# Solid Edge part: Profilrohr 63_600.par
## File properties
Username: ahadarics
Dokumentum tartalom típus: 0
Author: ahadarics
Last saved by: ahadarics
Revision: 93
Sűrűség: 0,000 kg/m^3
Pontosság: 0,990
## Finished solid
Body 1: solid body, 175 faces, 519 edges, 346 vertices.
  Faces by surface: cylinder 107, plane 68
  Edges by curve: line 305, circle 214
Bounding box of the edges (mm): 70.400 x 70.400 x 654.000, from (-35.2, -35.2, -614.5) to (35.2, 35.2, 39.5).
Cylindrical faces by radius (mm): R0.1 x16, R0.2 x30, R0.5 x28, R1 x8, R3.75 x8, R4.8 x4, R6 x4, R31.5 x1, R33.8 x8
Planar faces by outward normal: +x 6, +y 6, +z 1, -x 4, -y 4, -z 1, oblique 46
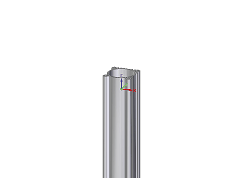
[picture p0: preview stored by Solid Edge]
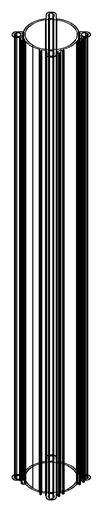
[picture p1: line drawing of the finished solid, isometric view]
